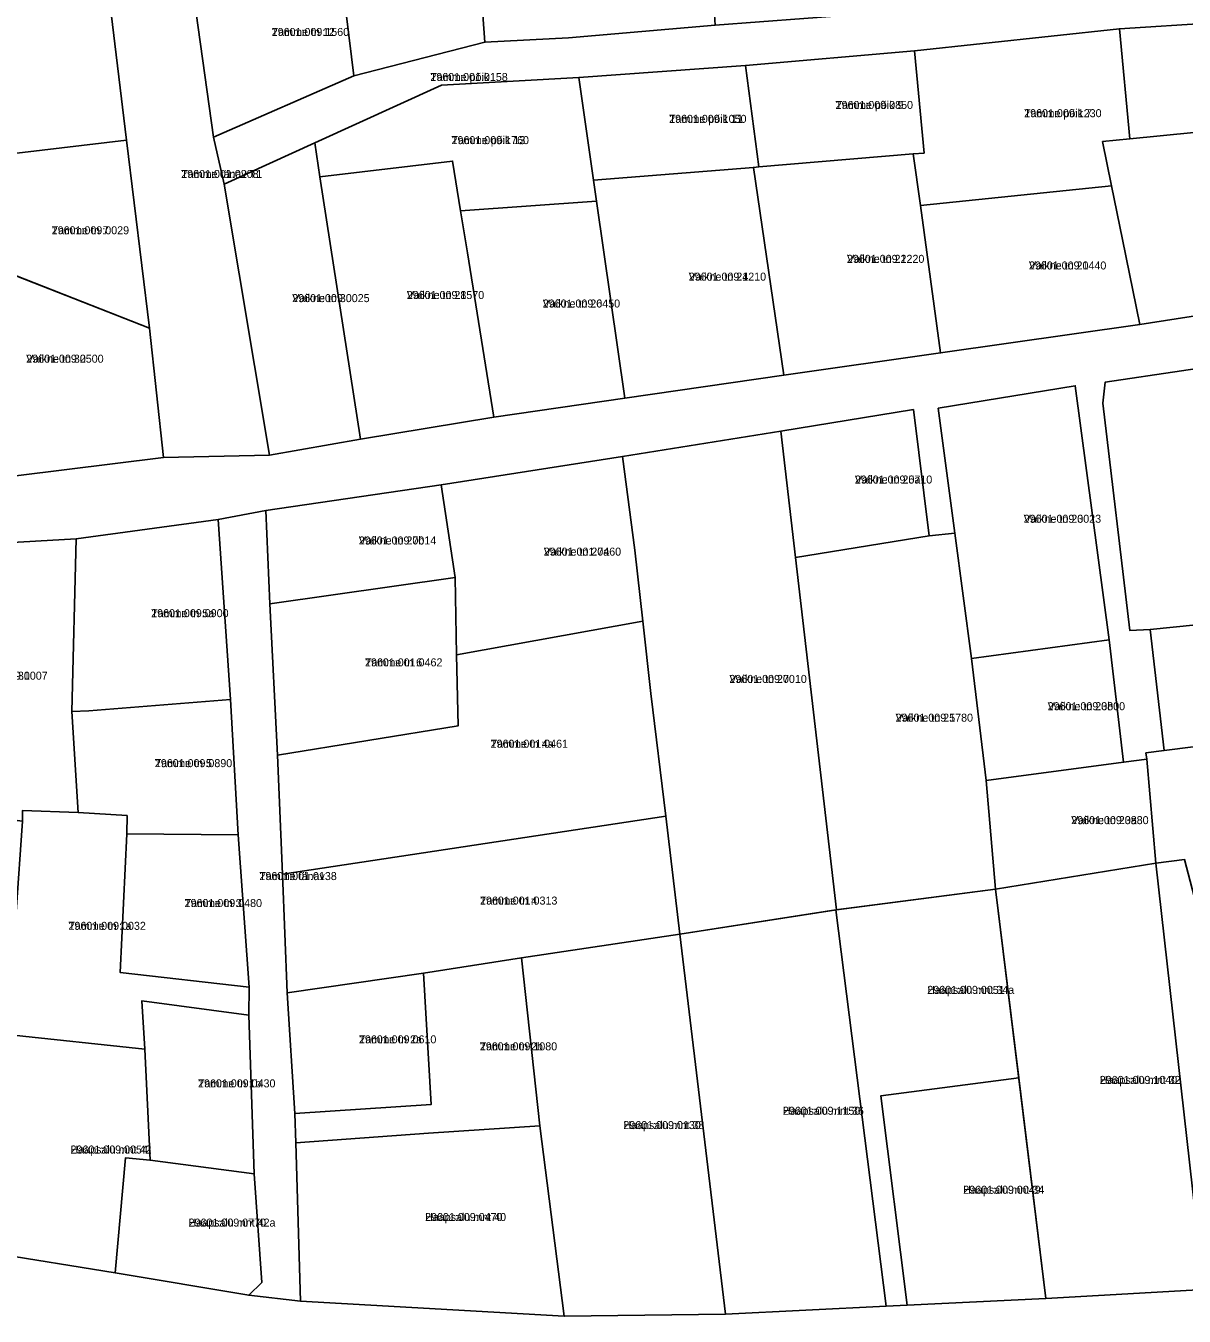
# Model space of a CAD drawing. Extents: x 518839 to 525192, y 6573164 to 6576561.
# Drawn here: x 522991.1 to 523208.1, y 6574453 to 6574694.8 of the extents above; entities that cross this region are included whole.
import ezdxf

# ---------------------------------------------------------------- set-up
doc = ezdxf.new("R2010")
doc.units = 0
for name, color, linetype in [('L_AADRESS', 7, 'Continuous'), ('PIIR', 7, 'Continuous'), ('TUNNUS', 7, 'Continuous')]:
    doc.layers.add(name, color=color, linetype=linetype)

msp = doc.modelspace()

# ---------------------------------------------------------------- linework, layer by layer
at = {"layer": 'PIIR'}
for points in [[(523009.93, 6574673.33), (523003.65, 6574724.97), (523017.74, 6574737.93), (523021.73, 6574706.13), (523026.19, 6574673.91), (523028.2, 6574665.06), (523036.69, 6574614.32), (523016.84, 6574613.87), (523014.21, 6574638.08)], [(522981, 6574708.25), (523003.65, 6574724.97), (523009.93, 6574673.33), (522985.63, 6574670.45)], [(523077.06, 6574691.67), (523075.26, 6574716.58), (523087.63, 6574717.93), (523112.27, 6574720.33), (523112.61, 6574721.22), (523118.52, 6574721.92), (523120.19, 6574694.88), (523092.73, 6574692.48)], [(523049.74, 6574707.8), (523049.16, 6574712.45), (523062.74, 6574714.6), (523075.26, 6574716.58), (523077.06, 6574691.67), (523052.51, 6574685.38)], [(523049.74, 6574707.8), (523052.51, 6574685.38), (523026.19, 6574673.91), (523021.73, 6574706.13)], [(523028.2, 6574665.06), (523026.19, 6574673.91), (523052.51, 6574685.38), (523077.06, 6574691.67), (523092.73, 6574692.48), (523120.19, 6574694.88), (523153.4, 6574697.39), (523186.91, 6574700.3), (523212.34, 6574702.46), (523230.21, 6574703.79), (523231.04, 6574696.45), (523195.92, 6574694.21), (523157.56, 6574690.05), (523125.9, 6574687.31), (523094.64, 6574685.06), (523068.9, 6574683.61), (523045.17, 6574672.84)], [(523231.04, 6574696.45), (523233.85, 6574677.17), (523197.86, 6574673.59), (523195.92, 6574694.21)], [(523159.33, 6574670.92), (523157.56, 6574690.05), (523195.92, 6574694.21), (523197.86, 6574673.59), (523192.78, 6574673.06), (523194.48, 6574664.75), (523158.65, 6574661.07), (523157.32, 6574670.77)], [(523125.9, 6574687.31), (523157.56, 6574690.05), (523159.33, 6574670.92), (523157.32, 6574670.77), (523128.36, 6574668.31)], [(523094.64, 6574685.06), (523125.9, 6574687.31), (523128.36, 6574668.31), (523127.36, 6574668.23), (523097.38, 6574665.86)], [(523068.9, 6574683.61), (523094.64, 6574685.06), (523097.38, 6574665.86), (523097.94, 6574661.91), (523072.5, 6574660.12), (523071.01, 6574669.42), (523046.14, 6574666.46), (523045.17, 6574672.84)], [(523237.4, 6574644.64), (523199.77, 6574638.82), (523196.52, 6574654.74), (523194.48, 6574664.75), (523192.78, 6574673.06), (523197.86, 6574673.59), (523233.85, 6574677.17)], [(522985.63, 6574670.45), (523009.93, 6574673.33), (523014.21, 6574638.08), (522978.32, 6574652.19)], [(523045.17, 6574672.84), (523046.14, 6574666.46), (523053.73, 6574617.31), (523036.69, 6574614.32), (523028.2, 6574665.06)], [(523053.73, 6574617.31), (523046.14, 6574666.46), (523071.01, 6574669.42), (523072.5, 6574660.12), (523073.77, 6574652.24), (523078.72, 6574621.41)], [(523133.09, 6574629.32), (523127.36, 6574668.23), (523128.36, 6574668.31), (523157.32, 6574670.77), (523158.65, 6574661.07), (523162.42, 6574633.47)], [(523103.27, 6574625.01), (523097.94, 6574661.91), (523097.38, 6574665.86), (523127.36, 6574668.23), (523133.09, 6574629.32)], [(523162.42, 6574633.47), (523158.65, 6574661.07), (523194.48, 6574664.75), (523196.52, 6574654.74), (523199.77, 6574638.82)], [(523078.72, 6574621.41), (523073.77, 6574652.24), (523072.5, 6574660.12), (523097.94, 6574661.91), (523103.27, 6574625.01)], [(522966.36, 6574637.92), (522970.97, 6574655.08), (523014.21, 6574638.08), (523016.84, 6574613.87), (522971.01, 6574608.2)], [(523192.82, 6574624.06), (523193.28, 6574628), (523221.88, 6574632.21), (523227, 6574586.83), (523227.56, 6574584.27), (523201.72, 6574581.64), (523197.9, 6574581.44)], [(523187.65, 6574627.33), (523194.01, 6574579.74), (523168.25, 6574576.22), (523165.12, 6574599.71), (523162, 6574623.1)], [(523132.53, 6574618.8), (523157.35, 6574622.85), (523160.29, 6574599.21), (523135.27, 6574595.14)], [(523113.57, 6574524.56), (523110.93, 6574546.66), (523108.17, 6574569.67), (523106.63, 6574583.21), (523105.17, 6574596.49), (523102.82, 6574614.06), (523132.53, 6574618.8), (523135.27, 6574595.14), (523142.91, 6574529.15)], [(523071.77, 6574576.92), (523071.5, 6574591.4), (523068.86, 6574608.74), (523102.82, 6574614.06), (523105.17, 6574596.49), (523106.63, 6574583.21)], [(523036.8, 6574586.43), (523036.05, 6574603.93), (523068.86, 6574608.74), (523071.5, 6574591.4)], [(523030.85, 6574543.16), (523029.41, 6574568.56), (523027.09, 6574602.28), (523036.05, 6574603.93), (523036.8, 6574586.43), (523038.2, 6574558.08), (523039.17, 6574535.78), (523039.99, 6574513.56), (523041.44, 6574490.99), (523041.66, 6574485.5), (523042.53, 6574455.82), (523032.83, 6574456.91), (523035.25, 6574459.3), (523033.85, 6574479.65), (523032.81, 6574509.41), (523032.9, 6574514.65)], [(522999.67, 6574566.3), (523000.51, 6574598.63), (523027.09, 6574602.28), (523029.41, 6574568.56), (523002.89, 6574566.41)], [(523135.27, 6574595.14), (523160.29, 6574599.21), (523165.12, 6574599.71), (523168.25, 6574576.22), (523170.99, 6574553.33), (523172.73, 6574532.99), (523142.91, 6574529.15)], [(522974.17, 6574570.61), (522960.48, 6574572.93), (522964.52, 6574596.6), (523000.51, 6574598.63), (522999.67, 6574566.3), (523000.83, 6574547.39), (522990.45, 6574547.74), (522990.42, 6574545.75), (522971.69, 6574548.11)], [(523038.2, 6574558.08), (523036.8, 6574586.43), (523071.5, 6574591.4), (523071.77, 6574576.92), (523072.06, 6574563.61)], [(523039.17, 6574535.78), (523038.2, 6574558.08), (523072.06, 6574563.61), (523071.77, 6574576.92), (523106.63, 6574583.21), (523108.17, 6574569.67), (523110.93, 6574546.66)], [(523204.3, 6574558.98), (523201.72, 6574581.64), (523227.56, 6574584.27), (523229.02, 6574571.57), (523229.31, 6574568.94), (523229.96, 6574562.22)], [(523168.25, 6574576.22), (523194.01, 6574579.74), (523196.72, 6574556.79), (523170.99, 6574553.33)], [(523010.01, 6574546.79), (523000.83, 6574547.39), (522999.67, 6574566.3), (523002.89, 6574566.41), (523029.41, 6574568.56), (523030.85, 6574543.16), (523009.96, 6574543.38)], [(523208.1, 6574538.57), (523202.76, 6574537.84), (523201.05, 6574557.37), (523200.89, 6574558.52), (523204.3, 6574558.98), (523229.96, 6574562.22), (523232.12, 6574542.26), (523232.73, 6574533.64), (523210.24, 6574530.44)], [(523170.99, 6574553.33), (523196.72, 6574556.79), (523201.05, 6574557.37), (523202.76, 6574537.84), (523172.73, 6574532.99)], [(522990.45, 6574547.74), (523000.83, 6574547.39), (523010.01, 6574546.79), (523009.96, 6574543.38), (523008.7, 6574517.41), (523032.9, 6574514.65), (523032.81, 6574509.41), (523012.8, 6574512.08), (523013.37, 6574503.03), (522987.54, 6574505.75), (522989.23, 6574528.74), (522990.42, 6574545.75)], [(523110.93, 6574546.66), (523113.57, 6574524.56), (523083.89, 6574520.11), (523065.58, 6574517.24), (523039.99, 6574513.56), (523039.17, 6574535.78)], [(523030.85, 6574543.16), (523032.9, 6574514.65), (523008.7, 6574517.41), (523009.96, 6574543.38)], [(523172.73, 6574532.99), (523202.76, 6574537.84), (523211.77, 6574457.97), (523182.12, 6574456.3)], [(523202.76, 6574537.84), (523208.1, 6574538.57), (523210.24, 6574530.44), (523232.73, 6574533.64), (523235.87, 6574489.63), (523237.41, 6574459.95), (523211.77, 6574457.97)], [(523142.81, 6574529.12), (523172.73, 6574532.99), (523177.06, 6574497.64), (523151.24, 6574494.3), (523156.2, 6574455.07), (523152.21, 6574454.88)], [(523152.21, 6574454.88), (523122.12, 6574453.34), (523113.57, 6574524.56), (523142.81, 6574529.12)], [(523087.34, 6574488.64), (523083.89, 6574520.11), (523113.57, 6574524.56), (523122.12, 6574453.34), (523091.93, 6574452.99)], [(523041.66, 6574485.5), (523041.44, 6574490.99), (523066.99, 6574492.64), (523065.58, 6574517.24), (523083.89, 6574520.11), (523087.34, 6574488.64), (523066.52, 6574487.31)], [(523039.99, 6574513.56), (523065.58, 6574517.24), (523066.99, 6574492.64), (523041.44, 6574490.99)], [(523033.85, 6574479.65), (523014.32, 6574482.22), (523013.37, 6574503.03), (523012.8, 6574512.08), (523032.81, 6574509.41)], [(522987.54, 6574505.75), (523013.37, 6574503.03), (523014.32, 6574482.22), (523009.7, 6574482.65), (523007.82, 6574461.09), (522984.54, 6574464.85)], [(523151.24, 6574494.3), (523177.06, 6574497.64), (523182.12, 6574456.3), (523156.2, 6574455.07)], [(523066.52, 6574487.31), (523087.34, 6574488.64), (523091.93, 6574452.99), (523042.53, 6574455.82), (523041.66, 6574485.5)], [(523009.7, 6574482.65), (523014.32, 6574482.22), (523033.85, 6574479.65), (523035.25, 6574459.3), (523032.83, 6574456.91), (523007.82, 6574461.09)]]:
    msp.add_lwpolyline(points, close=True, dxfattribs=at)
for points in [[(522971.01, 6574608.2), (523016.84, 6574613.87), (523036.69, 6574614.32), (523053.73, 6574617.31), (523078.72, 6574621.41), (523103.27, 6574625.01), (523133.09, 6574629.32), (523162.42, 6574633.47), (523199.77, 6574638.82), (523237.4, 6574644.64), (523279.72, 6574651.19), (523294.84, 6574653.21), (523337.24, 6574659.51), (523341.33, 6574660.04), (523363.81, 6574663.75), (523381.14, 6574666.32)], [(523221.88, 6574632.21), (523193.28, 6574628), (523192.82, 6574624.06), (523197.9, 6574581.44), (523201.72, 6574581.64), (523204.3, 6574558.98), (523200.89, 6574558.52), (523201.05, 6574557.37), (523196.72, 6574556.79), (523194.01, 6574579.74), (523187.65, 6574627.33), (523162, 6574623.1), (523165.12, 6574599.71), (523160.29, 6574599.21), (523157.35, 6574622.85), (523132.53, 6574618.8), (523102.82, 6574614.06), (523068.86, 6574608.74), (523036.05, 6574603.93), (523027.09, 6574602.28), (523000.51, 6574598.63), (522964.52, 6574596.6)], [(522984.54, 6574464.85), (523007.82, 6574461.09), (523032.83, 6574456.91), (523042.53, 6574455.82), (523091.93, 6574452.99), (523122.12, 6574453.34), (523152.21, 6574454.88), (523156.2, 6574455.07), (523182.12, 6574456.3), (523211.77, 6574457.97), (523237.41, 6574459.95), (523266.52, 6574461.43), (523261.01, 6574491.27), (523268.66, 6574491.72), (523269.88, 6574481.86), (523271.9, 6574461.67), (523301.99, 6574462.99), (523317.63, 6574460.76), (523340.58, 6574459.73), (523340.75, 6574460.73), (523353.78, 6574457.82), (523377.5, 6574455.78)]]:
    msp.add_lwpolyline(points, dxfattribs=at)

# ---------------------------------------------------------------- texts
at = {"layer": 'L_AADRESS'}
for s, p in [('Tamme tn 12', (523037.12, 6574692.86)), ('Tamme põik', (523066.84, 6574684.42)), ('Tamme põik 9', (523142.76, 6574679.18)), ('Tamme põik 7', (523178.09, 6574677.64)), ('Tamme põik 11', (523111.57, 6574676.58)), ('Tamme põik 13', (523070.81, 6574672.59)), ('Tamme tänav T1', (523020.17, 6574666.25)), ('Tamme tn 7', (522995.9, 6574655.7)), ('Vaikne tn 22', (523144.89, 6574650.35)), ('Vaikne tn 20', (523178.98, 6574649.11)), ('Vaikne tn 24', (523115.24, 6574647.01)), ('Vaikne tn 28', (523062.43, 6574643.57)), ('Vaikne tn 30', (523040.96, 6574642.99)), ('Vaikne tn 26', (523087.89, 6574641.98)), ('Vaikne tn 32', (522991.13, 6574631.64)), ('Vaikne tn 25a', (523146.37, 6574609)), ('Vaikne tn 23', (523178, 6574601.65)), ('Vaikne tn 27b', (523053.44, 6574597.58)), ('Vaikne tn 27a', (523088.08, 6574595.49)), ('Tamme tn 5a', (523014.54, 6574583.96)), ('Tamme tn 6', (523054.6, 6574574.74)), ('Vaikne tn 31', (522980.65, 6574572.25)), ('Vaikne tn 27', (523122.86, 6574571.64)), ('Vaikne tn 23b', (523182.49, 6574566.53)), ('Vaikne tn 25', (523154, 6574564.38)), ('Tamme tn 4a', (523078.13, 6574559.5)), ('Tamme tn 5', (523015.22, 6574555.86)), ('Vaikne tn 23a', (523186.9, 6574545.18)), ('Tamme tänav', (523034.81, 6574534.7)), ('Tamme tn 4', (523076.14, 6574530.11)), ('Tamme tn 3', (523020.8, 6574529.65)), ('Tamme tn 1a', (522999.04, 6574525.38)), ('Haapsalu mnt 34a', (523159.94, 6574513.38)), ('Tamme tn 2a', (523053.46, 6574504.11)), ('Tamme tn 2b', (523076.1, 6574502.8)), ('Haapsalu mnt 32', (523192.25, 6574496.51)), ('Tamme tn 1b', (523023.32, 6574495.86)), ('Haapsalu mnt 36', (523132.89, 6574490.73)), ('Haapsalu mnt 38', (523103, 6574488.05)), ('Haapsalu mnt 42', (522999.43, 6574483.47)), ('Haapsalu mnt 34', (523166.68, 6574475.93)), ('Haapsalu mnt 42a', (523021.55, 6574469.78)), ('Haapsalu mnt 40', (523065.86, 6574470.82))]:
    msp.add_text(s, height=1.5, dxfattribs=at).set_placement(p)
at = {"layer": 'TUNNUS'}
for s, p in [('29601:009:1560', (523037.12, 6574692.86)), ('29601:001:0158', (523066.84, 6574684.42)), ('29601:009:0850', (523142.76, 6574679.18)), ('29601:009:1230', (523178.09, 6574677.64)), ('29601:009:1050', (523111.57, 6574676.58)), ('29601:009:1760', (523070.81, 6574672.59)), ('29601:001:0208', (523020.17, 6574666.25)), ('29601:009:0029', (522995.9, 6574655.7)), ('29601:009:1220', (523144.89, 6574650.35)), ('29601:009:1440', (523178.98, 6574649.11)), ('29601:009:1210', (523115.24, 6574647.01)), ('29601:009:1570', (523062.43, 6574643.57)), ('29601:009:0025', (523040.96, 6574642.99)), ('29601:009:0450', (523087.89, 6574641.98)), ('29601:009:0500', (522991.13, 6574631.64)), ('29601:009:0710', (523146.37, 6574609)), ('29601:009:0023', (523178, 6574601.65)), ('29601:009:0014', (523053.44, 6574597.58)), ('29601:001:0460', (523088.08, 6574595.49)), ('29601:009:0900', (523014.54, 6574583.96)), ('29601:001:0462', (523054.6, 6574574.74)), ('29601:009:0007', (522980.65, 6574572.25)), ('29601:009:0010', (523122.86, 6574571.64)), ('29601:009:0800', (523182.49, 6574566.53)), ('29601:009:1780', (523154, 6574564.38)), ('29601:001:0461', (523078.13, 6574559.5)), ('29601:009:0890', (523015.22, 6574555.86)), ('29601:009:0880', (523186.9, 6574545.18)), ('29601:001:0138', (523034.81, 6574534.7)), ('29601:001:0313', (523076.14, 6574530.11)), ('29601:009:0480', (523020.8, 6574529.65)), ('29601:009:0032', (522999.04, 6574525.38)), ('29601:009:0051', (523159.94, 6574513.38)), ('29601:009:0610', (523053.46, 6574504.11)), ('29601:009:1080', (523076.1, 6574502.8)), ('29601:009:1040', (523192.25, 6574496.51)), ('29601:009:0430', (523023.32, 6574495.86)), ('29601:009:1150', (523132.89, 6574490.73)), ('29601:009:0130', (523103, 6574488.05)), ('29601:009:0054', (522999.43, 6574483.47)), ('29601:009:0049', (523166.68, 6574475.93)), ('29601:009:0770', (523021.55, 6574469.78)), ('29601:009:0470', (523065.86, 6574470.82))]:
    msp.add_text(s, height=1.5, dxfattribs=at).set_placement(p)

doc.saveas('drawing.dxf')
